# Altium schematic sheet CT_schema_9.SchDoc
size 297 x 239 mm
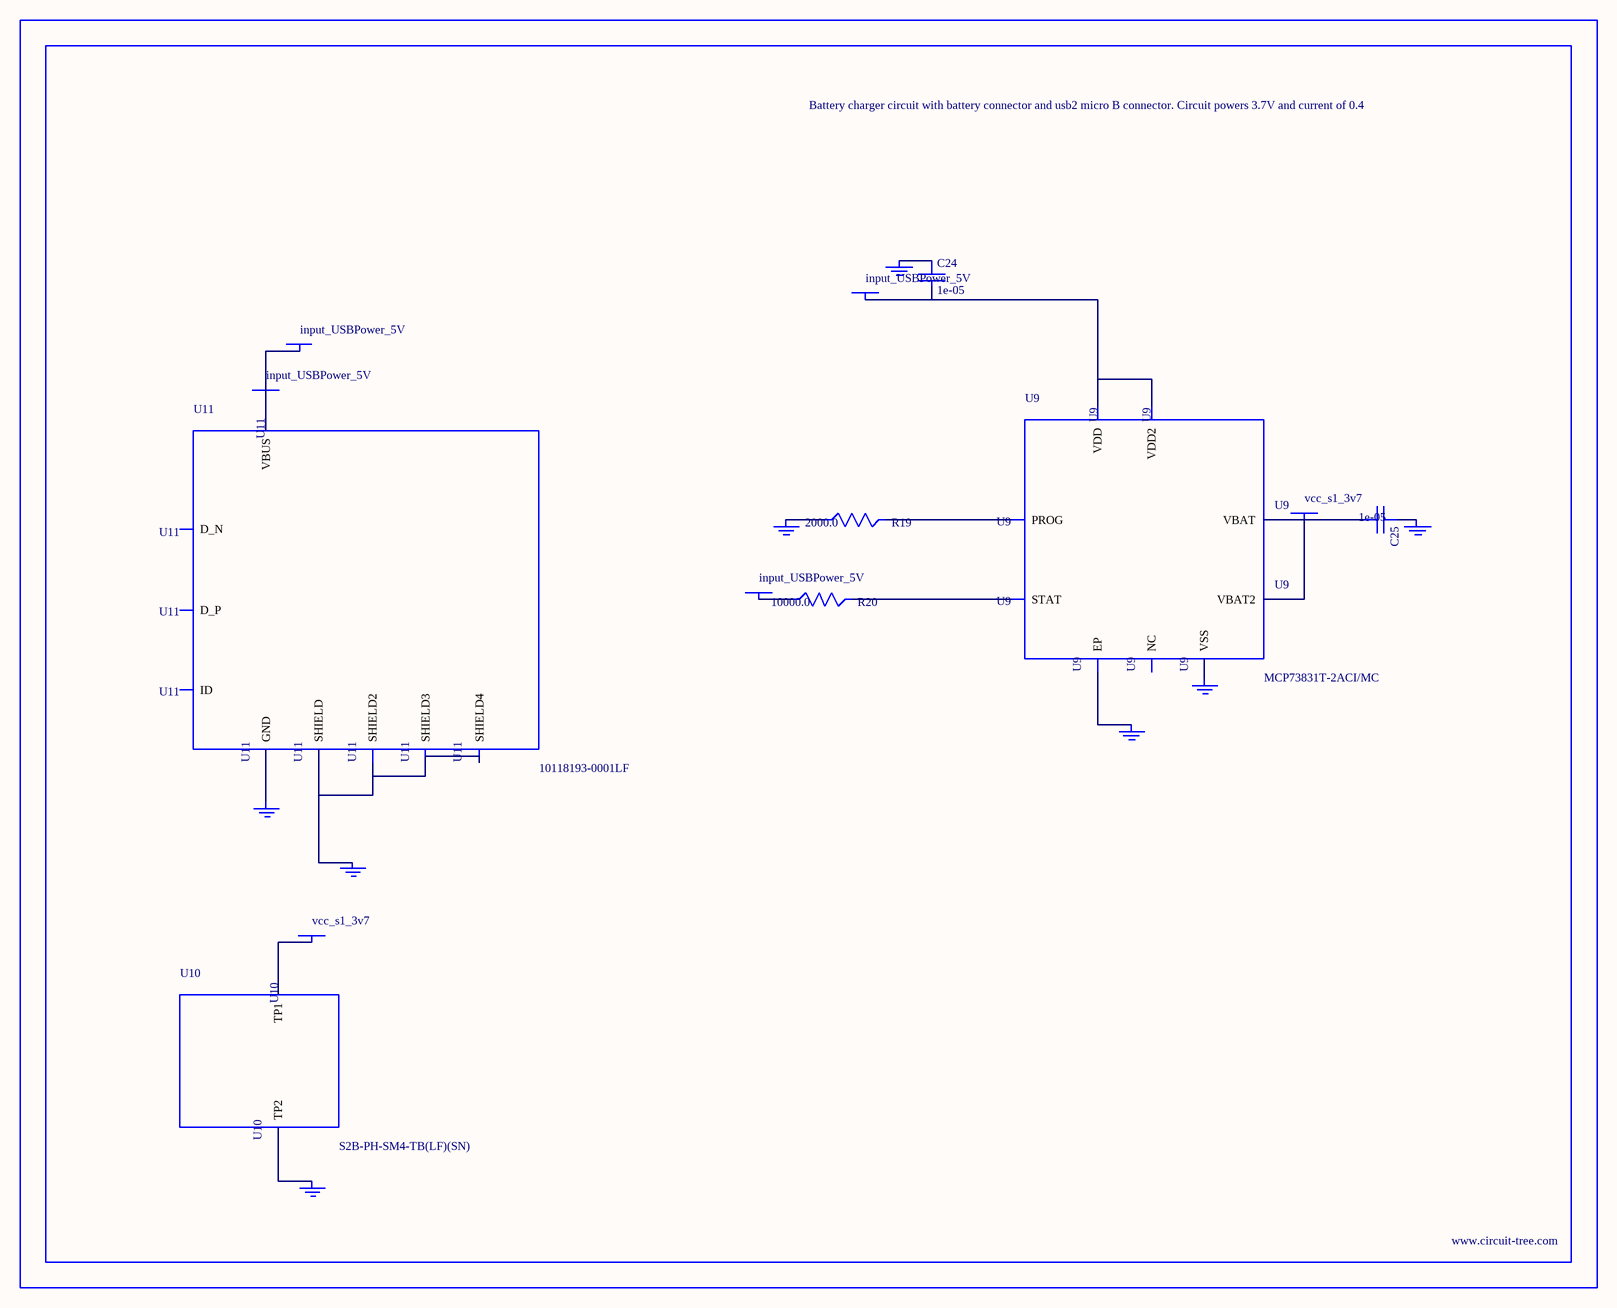
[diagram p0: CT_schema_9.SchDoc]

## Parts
BORDER8  (no value)
C24  1e-05  [C1206]
C25  1e-05  [C1206]
GND_INSTANCE_8_0  (no value)
GND_INSTANCE_8_1  (no value)
GND_INSTANCE_8_2  (no value)
GND_INSTANCE_8_3  (no value)
GND_INSTANCE_8_4  (no value)
GND_INSTANCE_8_5  (no value)
GND_INSTANCE_8_6  (no value)
GND_INSTANCE_8_7  (no value)
POWER_INSTANCE_8_0  input_USBPower_5V
POWER_INSTANCE_8_1  input_USBPower_5V
POWER_INSTANCE_8_2  vcc_s1_3v7
POWER_INSTANCE_8_3  vcc_s1_3v7
POWER_INSTANCE_8_4  input_USBPower_5V
POWER_INSTANCE_8_5  input_USBPower_5V
R19  2000.0  [R0603]
R20  10000.0  [R0603]
U9  MCP73831T-2ACI/MC  [DFN8_2X3MC]
U10  S2B-PH-SM4-TB(LF)(SN)  [JST-2-SMD]
U11  10118193-0001LF  [FCI_10118193-0001LF]

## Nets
NetC24_1: C24.1 GND_INSTANCE_8_0.0(GND)
NetC24_2: C24.2 POWER_INSTANCE_8_0.0(PWR) U9.1(VDD) U9.2(VDD2)
NetC25_1: C25.1 GND_INSTANCE_8_1.0(GND)
NetC25_2: C25.2 POWER_INSTANCE_8_2.0(PWR) U9.3(VBAT) U9.4(VBAT2)
NetGND_INSTANCE_8_2_0: GND_INSTANCE_8_2.0(GND) R19.1
NetGND_INSTANCE_8_3_0: GND_INSTANCE_8_3.0(GND) U9.9(EP)
NetGND_INSTANCE_8_4_0: GND_INSTANCE_8_4.0(GND) U9.6(VSS)
NetGND_INSTANCE_8_5_0: GND_INSTANCE_8_5.0(GND) U10.2(TP2)
NetGND_INSTANCE_8_6_0: GND_INSTANCE_8_6.0(GND) U11.6(SHIELD) U11.7(SHIELD2) U11.8(SHIELD3) U11.9(SHIELD4)
NetGND_INSTANCE_8_7_0: GND_INSTANCE_8_7.0(GND) U11.5(GND)
NetPOWER_INSTANCE_8_1_0: POWER_INSTANCE_8_1.0(PWR) R20.1
NetPOWER_INSTANCE_8_3_0: POWER_INSTANCE_8_3.0(PWR) U10.1(TP1)
NetPOWER_INSTANCE_8_4_0: POWER_INSTANCE_8_4.0(PWR) POWER_INSTANCE_8_5.0(PWR) U11.1(VBUS)
NetR19_2: R19.2 U9.8(PROG)
NetR20_2: R20.2 U9.5(STAT)

Not connected (* = marked no-connect by the designer): U9 7(NC); U11 2(D_N) 3(D_P) 4(ID)

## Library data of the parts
BORDER8 = BORDER_PAGE8
C24 C25 = C1206C106K3RACTU
GND_INSTANCE_8_0-GND_INSTANCE_8_7 = GND
POWER_INSTANCE_8_0-POWER_INSTANCE_8_5 = PWR
R19 = RC0603JR-072KL
R20 = RC0603JR-0710KL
